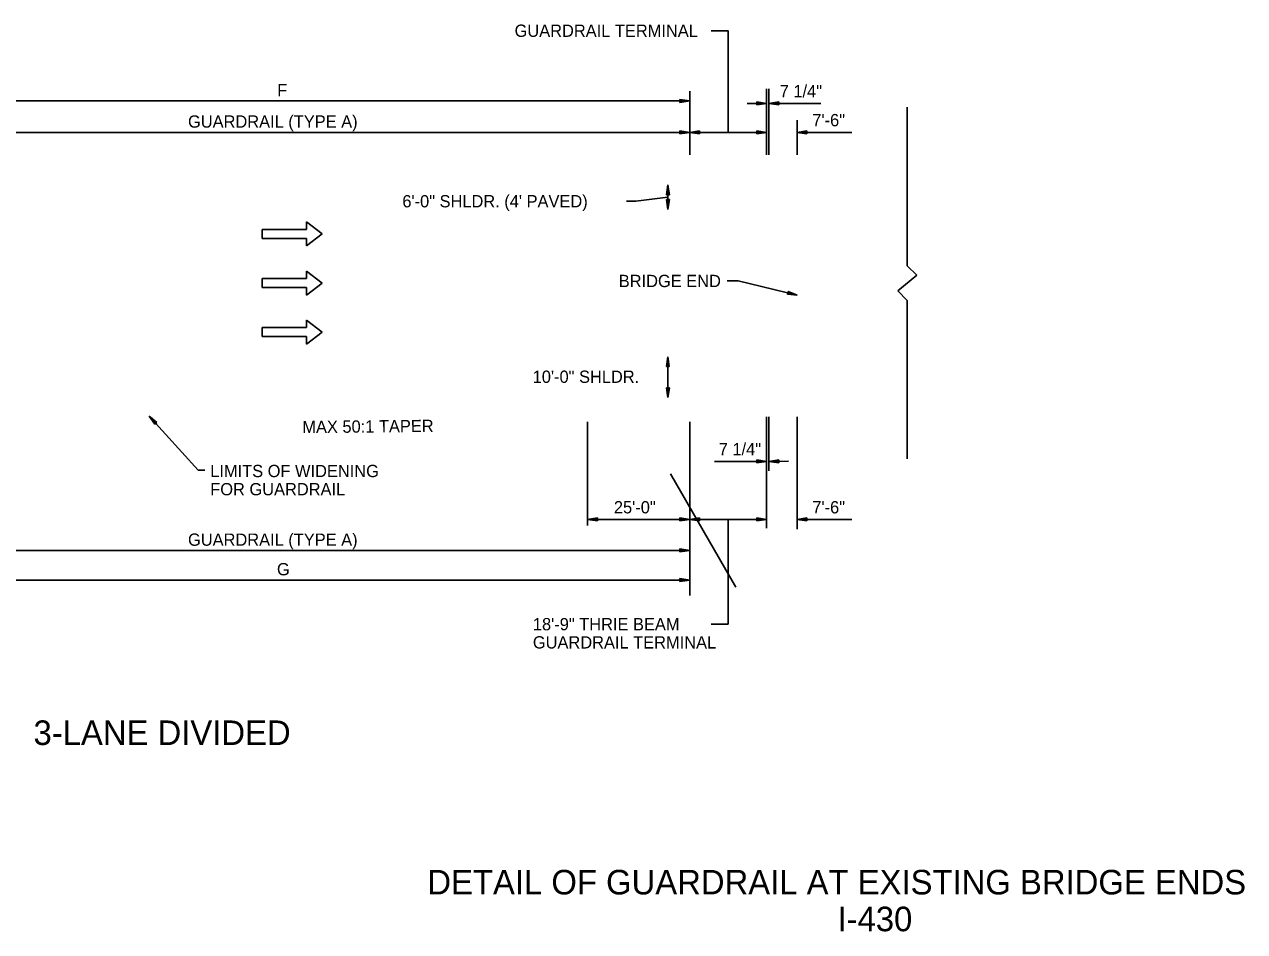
# Model space of a CAD drawing. Extents: x 1373853 to 1374003, y 380191 to 380927.
# Drawn here: x 1373883.7 to 1373943.4, y 380192.7 to 380237.1 of the extents above; entities that cross this region are included whole.
import ezdxf

# ---------------------------------------------------------------- set-up
doc = ezdxf.new("R2010")
doc.units = 0
for name, color, linetype in [('2', 7, 'Continuous'), ('7', 7, 'Continuous'), ('8', 7, 'Continuous'), ('Default', 7, 'Continuous'), ('E_Existing ROW', 7, 'Continuous'), ('R_Guardrail_Widening', 7, 'Continuous')]:
    doc.layers.add(name, color=color, linetype=linetype)

msp = doc.modelspace()

# ---------------------------------------------------------------- linework, layer by layer
at = {"layer": '2'}
for p, q in [((1373916.236, 380230.714), (1373916.236, 380233.821)), ((1373919.986, 380230.714), (1373919.986, 380233.941)), ((1373920.107, 380230.714), (1373920.107, 380233.941)), ((1373876.236, 380233.341), (1373916.236, 380233.341)), ((1373919.986, 380233.22), (1373919.045, 380233.22)), ((1373922.65, 380233.22), (1373920.107, 380233.22)), ((1373921.486, 380230.714), (1373921.486, 380232.406)), ((1373876.236, 380231.806), (1373916.236, 380231.806)), ((1373916.236, 380231.806), (1373919.986, 380231.806)), ((1373921.486, 380231.806), (1373924.16, 380231.806)), ((1373915.169, 380228.041), (1373915.166, 380229.241)), ((1373918.056, 380224.543), (1373918.603, 380224.543)), ((1373921.486, 380223.854), (1373918.603, 380224.543)), ((1373915.169, 380218.841), (1373915.164, 380220.841)), ((1373889.802, 380217.937), (1373892.201, 380215.286)), ((1373911.236, 380212.592), (1373911.236, 380217.66)), ((1373916.236, 380209.174), (1373916.236, 380217.66)), ((1373919.986, 380212.463), (1373919.986, 380217.902)), ((1373920.107, 380215.258), (1373920.107, 380217.902)), ((1373921.486, 380212.402), (1373921.486, 380217.902)), ((1373917.442, 380215.722), (1373919.986, 380215.722)), ((1373920.107, 380215.722), (1373921.067, 380215.725)), ((1373892.201, 380215.286), (1373892.52, 380215.286)), ((1373911.236, 380212.881), (1373916.236, 380212.881)), ((1373916.236, 380212.881), (1373919.986, 380212.881)), ((1373921.486, 380212.881), (1373924.16, 380212.881)), ((1373876.236, 380211.366), (1373916.236, 380211.366)), ((1373876.236, 380209.921), (1373916.236, 380209.921))]:
    msp.add_line(p, q, dxfattribs=at)
for points in [[(1373918.111, 380231.806), (1373918.111, 380236.776), (1373917.276, 380236.776)], [(1373913.145, 380228.441), (1373913.593, 380228.441), (1373915.167, 380228.641)], [(1373918.111, 380212.881), (1373918.111, 380207.765), (1373917.276, 380207.765)]]:
    msp.add_lwpolyline(points, dxfattribs=at)
at = {"layer": '7'}
for p, q in [((1373915.756, 380233.415), (1373916.236, 380233.341)), ((1373915.756, 380233.415), (1373915.756, 380233.269)), ((1373915.756, 380233.4), (1373916.155, 380233.341)), ((1373915.756, 380233.388), (1373916.073, 380233.341)), ((1373915.756, 380233.376), (1373915.992, 380233.341)), ((1373915.756, 380233.365), (1373915.913, 380233.341)), ((1373915.756, 380233.353), (1373915.832, 380233.341)), ((1373915.756, 380233.269), (1373916.236, 380233.341)), ((1373915.756, 380233.319), (1373915.913, 380233.341)), ((1373915.756, 380233.295), (1373916.073, 380233.341)), ((1373915.756, 380233.281), (1373916.155, 380233.341)), ((1373915.756, 380233.305), (1373915.992, 380233.341)), ((1373915.756, 380233.331), (1373915.832, 380233.341)), ((1373919.506, 380233.294), (1373919.986, 380233.22)), ((1373919.506, 380233.294), (1373919.506, 380233.148)), ((1373919.506, 380233.279), (1373919.905, 380233.22)), ((1373919.506, 380233.268), (1373919.823, 380233.22)), ((1373919.506, 380233.256), (1373919.742, 380233.22)), ((1373919.506, 380233.244), (1373919.663, 380233.22)), ((1373919.506, 380233.232), (1373919.582, 380233.22)), ((1373919.506, 380233.148), (1373919.986, 380233.22)), ((1373919.506, 380233.198), (1373919.663, 380233.22)), ((1373919.506, 380233.174), (1373919.823, 380233.22)), ((1373919.506, 380233.16), (1373919.905, 380233.22)), ((1373919.506, 380233.184), (1373919.742, 380233.22)), ((1373919.506, 380233.21), (1373919.582, 380233.22)), ((1373920.587, 380233.294), (1373920.107, 380233.22)), ((1373920.587, 380233.148), (1373920.107, 380233.22)), ((1373920.587, 380233.279), (1373920.188, 380233.22)), ((1373920.587, 380233.16), (1373920.188, 380233.22)), ((1373920.587, 380233.268), (1373920.269, 380233.22)), ((1373920.587, 380233.174), (1373920.269, 380233.22)), ((1373920.587, 380233.256), (1373920.35, 380233.22)), ((1373920.587, 380233.184), (1373920.35, 380233.22)), ((1373920.587, 380233.244), (1373920.429, 380233.22)), ((1373920.587, 380233.198), (1373920.429, 380233.22)), ((1373920.587, 380233.232), (1373920.51, 380233.22)), ((1373920.587, 380233.21), (1373920.51, 380233.22)), ((1373920.587, 380233.294), (1373920.587, 380233.148)), ((1373915.756, 380231.88), (1373916.236, 380231.806)), ((1373915.756, 380231.88), (1373915.756, 380231.734)), ((1373915.756, 380231.865), (1373916.155, 380231.806)), ((1373915.756, 380231.853), (1373916.073, 380231.806)), ((1373915.756, 380231.841), (1373915.992, 380231.806)), ((1373915.756, 380231.829), (1373915.913, 380231.806)), ((1373915.756, 380231.818), (1373915.832, 380231.806)), ((1373915.756, 380231.734), (1373916.236, 380231.806)), ((1373915.756, 380231.784), (1373915.913, 380231.806)), ((1373915.756, 380231.76), (1373916.073, 380231.806)), ((1373915.756, 380231.746), (1373916.155, 380231.806)), ((1373915.756, 380231.77), (1373915.992, 380231.806)), ((1373915.756, 380231.796), (1373915.832, 380231.806)), ((1373916.716, 380231.88), (1373916.236, 380231.806)), ((1373916.716, 380231.734), (1373916.236, 380231.806)), ((1373916.716, 380231.865), (1373916.317, 380231.806)), ((1373916.716, 380231.746), (1373916.317, 380231.806)), ((1373916.716, 380231.853), (1373916.398, 380231.806)), ((1373916.716, 380231.76), (1373916.398, 380231.806)), ((1373916.716, 380231.841), (1373916.479, 380231.806)), ((1373916.716, 380231.77), (1373916.479, 380231.806)), ((1373916.716, 380231.829), (1373916.558, 380231.806)), ((1373916.716, 380231.784), (1373916.558, 380231.806)), ((1373916.716, 380231.818), (1373916.639, 380231.806)), ((1373916.716, 380231.796), (1373916.639, 380231.806)), ((1373916.716, 380231.88), (1373916.716, 380231.734)), ((1373919.506, 380231.88), (1373919.986, 380231.806)), ((1373919.506, 380231.88), (1373919.506, 380231.734)), ((1373919.506, 380231.865), (1373919.905, 380231.806)), ((1373919.506, 380231.853), (1373919.823, 380231.806)), ((1373919.506, 380231.841), (1373919.742, 380231.806)), ((1373919.506, 380231.829), (1373919.663, 380231.806)), ((1373919.506, 380231.818), (1373919.582, 380231.806)), ((1373919.506, 380231.734), (1373919.986, 380231.806)), ((1373919.506, 380231.784), (1373919.663, 380231.806)), ((1373919.506, 380231.76), (1373919.823, 380231.806)), ((1373919.506, 380231.746), (1373919.905, 380231.806)), ((1373919.506, 380231.77), (1373919.742, 380231.806)), ((1373919.506, 380231.796), (1373919.582, 380231.806)), ((1373921.966, 380231.88), (1373921.486, 380231.806)), ((1373921.966, 380231.734), (1373921.486, 380231.806)), ((1373921.966, 380231.865), (1373921.567, 380231.806)), ((1373921.966, 380231.746), (1373921.567, 380231.806)), ((1373921.966, 380231.853), (1373921.648, 380231.806)), ((1373921.966, 380231.76), (1373921.648, 380231.806)), ((1373921.966, 380231.841), (1373921.729, 380231.806)), ((1373921.966, 380231.77), (1373921.729, 380231.806)), ((1373921.966, 380231.829), (1373921.808, 380231.806)), ((1373921.966, 380231.784), (1373921.808, 380231.806)), ((1373921.966, 380231.818), (1373921.889, 380231.806)), ((1373921.966, 380231.796), (1373921.889, 380231.806)), ((1373921.966, 380231.88), (1373921.966, 380231.734)), ((1373915.094, 380228.761), (1373915.166, 380229.241)), ((1373915.106, 380228.761), (1373915.166, 380229.16)), ((1373915.118, 380228.761), (1373915.166, 380229.079)), ((1373915.13, 380228.761), (1373915.166, 380228.998)), ((1373915.142, 380228.761), (1373915.166, 380228.916)), ((1373915.154, 380228.761), (1373915.166, 380228.838)), ((1373915.237, 380228.761), (1373915.166, 380229.241)), ((1373915.226, 380228.761), (1373915.166, 380229.16)), ((1373915.214, 380228.761), (1373915.166, 380229.079)), ((1373915.202, 380228.761), (1373915.166, 380228.998)), ((1373915.19, 380228.761), (1373915.166, 380228.916)), ((1373915.178, 380228.761), (1373915.166, 380228.838)), ((1373915.237, 380228.761), (1373915.094, 380228.761)), ((1373915.095, 380228.521), (1373915.169, 380228.041)), ((1373915.095, 380228.521), (1373915.24, 380228.521)), ((1373915.109, 380228.521), (1373915.169, 380228.122)), ((1373915.121, 380228.521), (1373915.169, 380228.204)), ((1373915.133, 380228.521), (1373915.169, 380228.285)), ((1373915.145, 380228.521), (1373915.169, 380228.364)), ((1373915.157, 380228.521), (1373915.169, 380228.445)), ((1373915.24, 380228.521), (1373915.169, 380228.041)), ((1373915.19, 380228.521), (1373915.169, 380228.364)), ((1373915.214, 380228.521), (1373915.169, 380228.204)), ((1373915.228, 380228.521), (1373915.169, 380228.122)), ((1373915.205, 380228.521), (1373915.169, 380228.285)), ((1373915.178, 380228.521), (1373915.169, 380228.445)), ((1373921.005, 380223.896), (1373921.038, 380224.035)), ((1373921.032, 380224.012), (1373921.328, 380223.892)), ((1373921.035, 380224.023), (1373921.409, 380223.872)), ((1373921.038, 380224.035), (1373921.486, 380223.854)), ((1373921.005, 380223.896), (1373921.486, 380223.854)), ((1373921.007, 380223.907), (1373921.409, 380223.872)), ((1373921.01, 380223.919), (1373921.328, 380223.892)), ((1373921.013, 380223.93), (1373921.249, 380223.911)), ((1373921.016, 380223.942), (1373921.172, 380223.929)), ((1373921.018, 380223.954), (1373921.093, 380223.948)), ((1373921.023, 380223.974), (1373921.093, 380223.948)), ((1373921.027, 380223.988), (1373921.172, 380223.929)), ((1373921.03, 380224), (1373921.249, 380223.911)), ((1373915.092, 380220.361), (1373915.164, 380220.841)), ((1373915.104, 380220.361), (1373915.164, 380220.76)), ((1373915.116, 380220.361), (1373915.164, 380220.679)), ((1373915.128, 380220.361), (1373915.164, 380220.598)), ((1373915.14, 380220.361), (1373915.164, 380220.516)), ((1373915.152, 380220.361), (1373915.164, 380220.438)), ((1373915.235, 380220.361), (1373915.164, 380220.841)), ((1373915.224, 380220.361), (1373915.164, 380220.76)), ((1373915.212, 380220.361), (1373915.164, 380220.679)), ((1373915.2, 380220.361), (1373915.164, 380220.598)), ((1373915.188, 380220.361), (1373915.164, 380220.516)), ((1373915.176, 380220.361), (1373915.164, 380220.438)), ((1373915.235, 380220.361), (1373915.092, 380220.361)), ((1373915.095, 380219.321), (1373915.169, 380218.841)), ((1373915.095, 380219.321), (1373915.24, 380219.321)), ((1373915.109, 380219.321), (1373915.169, 380218.922)), ((1373915.121, 380219.321), (1373915.169, 380219.004)), ((1373915.133, 380219.321), (1373915.169, 380219.085)), ((1373915.145, 380219.321), (1373915.169, 380219.164)), ((1373915.157, 380219.321), (1373915.169, 380219.245)), ((1373915.24, 380219.321), (1373915.169, 380218.841)), ((1373915.19, 380219.321), (1373915.169, 380219.164)), ((1373915.214, 380219.321), (1373915.169, 380219.004)), ((1373915.228, 380219.321), (1373915.169, 380218.922)), ((1373915.205, 380219.321), (1373915.169, 380219.085)), ((1373915.178, 380219.321), (1373915.169, 380219.245)), ((1373890.177, 380217.628), (1373889.802, 380217.937)), ((1373890.07, 380217.534), (1373889.802, 380217.937)), ((1373890.169, 380217.622), (1373889.857, 380217.879)), ((1373890.081, 380217.54), (1373889.857, 380217.879)), ((1373890.092, 380217.55), (1373889.913, 380217.816)), ((1373890.158, 380217.614), (1373889.913, 380217.816)), ((1373890.15, 380217.605), (1373889.965, 380217.758)), ((1373890.098, 380217.559), (1373889.965, 380217.758)), ((1373890.106, 380217.565), (1373890.018, 380217.698)), ((1373890.139, 380217.597), (1373890.018, 380217.698)), ((1373890.177, 380217.628), (1373890.07, 380217.534)), ((1373890.114, 380217.574), (1373890.074, 380217.637)), ((1373890.133, 380217.586), (1373890.074, 380217.637)), ((1373919.506, 380215.796), (1373919.986, 380215.722)), ((1373919.506, 380215.796), (1373919.506, 380215.651)), ((1373919.506, 380215.782), (1373919.905, 380215.722)), ((1373919.506, 380215.77), (1373919.823, 380215.722)), ((1373919.506, 380215.758), (1373919.742, 380215.722)), ((1373919.506, 380215.746), (1373919.663, 380215.722)), ((1373919.506, 380215.734), (1373919.582, 380215.722)), ((1373919.506, 380215.651), (1373919.986, 380215.722)), ((1373919.506, 380215.701), (1373919.663, 380215.722)), ((1373919.506, 380215.677), (1373919.823, 380215.722)), ((1373919.506, 380215.663), (1373919.905, 380215.722)), ((1373919.506, 380215.687), (1373919.742, 380215.722)), ((1373919.506, 380215.713), (1373919.582, 380215.722)), ((1373920.587, 380215.796), (1373920.107, 380215.722)), ((1373920.587, 380215.651), (1373920.107, 380215.722)), ((1373920.587, 380215.782), (1373920.188, 380215.722)), ((1373920.587, 380215.663), (1373920.188, 380215.722)), ((1373920.587, 380215.77), (1373920.269, 380215.722)), ((1373920.587, 380215.677), (1373920.269, 380215.722)), ((1373920.587, 380215.758), (1373920.35, 380215.722)), ((1373920.587, 380215.687), (1373920.35, 380215.722)), ((1373920.587, 380215.746), (1373920.429, 380215.722)), ((1373920.587, 380215.701), (1373920.429, 380215.722)), ((1373920.587, 380215.734), (1373920.51, 380215.722)), ((1373920.587, 380215.713), (1373920.51, 380215.722)), ((1373920.587, 380215.796), (1373920.587, 380215.651)), ((1373911.716, 380212.956), (1373911.236, 380212.881)), ((1373911.716, 380212.81), (1373911.236, 380212.881)), ((1373911.716, 380212.941), (1373911.317, 380212.881)), ((1373911.716, 380212.822), (1373911.317, 380212.881)), ((1373911.716, 380212.929), (1373911.398, 380212.881)), ((1373911.716, 380212.836), (1373911.398, 380212.881)), ((1373911.716, 380212.917), (1373911.479, 380212.881)), ((1373911.716, 380212.846), (1373911.479, 380212.881)), ((1373911.716, 380212.905), (1373911.558, 380212.881)), ((1373911.716, 380212.86), (1373911.558, 380212.881)), ((1373911.716, 380212.893), (1373911.639, 380212.881)), ((1373911.716, 380212.872), (1373911.639, 380212.881)), ((1373911.716, 380212.956), (1373911.716, 380212.81)), ((1373915.756, 380212.956), (1373916.236, 380212.881)), ((1373915.756, 380212.956), (1373915.756, 380212.81)), ((1373915.756, 380212.941), (1373916.155, 380212.881)), ((1373915.756, 380212.929), (1373916.073, 380212.881)), ((1373915.756, 380212.917), (1373915.992, 380212.881)), ((1373915.756, 380212.905), (1373915.913, 380212.881)), ((1373915.756, 380212.893), (1373915.832, 380212.881)), ((1373915.756, 380212.81), (1373916.236, 380212.881)), ((1373915.756, 380212.86), (1373915.913, 380212.881)), ((1373915.756, 380212.836), (1373916.073, 380212.881)), ((1373915.756, 380212.822), (1373916.155, 380212.881)), ((1373915.756, 380212.846), (1373915.992, 380212.881)), ((1373915.756, 380212.872), (1373915.832, 380212.881)), ((1373916.716, 380212.956), (1373916.236, 380212.881)), ((1373916.716, 380212.81), (1373916.236, 380212.881)), ((1373916.716, 380212.941), (1373916.317, 380212.881)), ((1373916.716, 380212.822), (1373916.317, 380212.881)), ((1373916.716, 380212.929), (1373916.398, 380212.881)), ((1373916.716, 380212.836), (1373916.398, 380212.881)), ((1373916.716, 380212.917), (1373916.479, 380212.881)), ((1373916.716, 380212.846), (1373916.479, 380212.881)), ((1373916.716, 380212.905), (1373916.558, 380212.881)), ((1373916.716, 380212.86), (1373916.558, 380212.881)), ((1373916.716, 380212.893), (1373916.639, 380212.881)), ((1373916.716, 380212.872), (1373916.639, 380212.881)), ((1373916.716, 380212.956), (1373916.716, 380212.81)), ((1373919.506, 380212.956), (1373919.986, 380212.881)), ((1373919.506, 380212.956), (1373919.506, 380212.81)), ((1373919.506, 380212.941), (1373919.905, 380212.881)), ((1373919.506, 380212.929), (1373919.823, 380212.881)), ((1373919.506, 380212.917), (1373919.742, 380212.881)), ((1373919.506, 380212.905), (1373919.663, 380212.881)), ((1373919.506, 380212.893), (1373919.582, 380212.881)), ((1373919.506, 380212.81), (1373919.986, 380212.881)), ((1373919.506, 380212.86), (1373919.663, 380212.881)), ((1373919.506, 380212.836), (1373919.823, 380212.881)), ((1373919.506, 380212.822), (1373919.905, 380212.881)), ((1373919.506, 380212.846), (1373919.742, 380212.881)), ((1373919.506, 380212.872), (1373919.582, 380212.881)), ((1373921.966, 380212.956), (1373921.486, 380212.881)), ((1373921.966, 380212.81), (1373921.486, 380212.881)), ((1373921.966, 380212.941), (1373921.567, 380212.881)), ((1373921.966, 380212.822), (1373921.567, 380212.881)), ((1373921.966, 380212.929), (1373921.648, 380212.881)), ((1373921.966, 380212.836), (1373921.648, 380212.881)), ((1373921.966, 380212.917), (1373921.729, 380212.881)), ((1373921.966, 380212.846), (1373921.729, 380212.881)), ((1373921.966, 380212.905), (1373921.808, 380212.881)), ((1373921.966, 380212.86), (1373921.808, 380212.881)), ((1373921.966, 380212.893), (1373921.889, 380212.881)), ((1373921.966, 380212.872), (1373921.889, 380212.881)), ((1373921.966, 380212.956), (1373921.966, 380212.81)), ((1373915.756, 380211.44), (1373916.236, 380211.366)), ((1373915.756, 380211.44), (1373915.756, 380211.294)), ((1373915.756, 380211.425), (1373916.155, 380211.366)), ((1373915.756, 380211.413), (1373916.073, 380211.366)), ((1373915.756, 380211.401), (1373915.992, 380211.366)), ((1373915.756, 380211.39), (1373915.913, 380211.366)), ((1373915.756, 380211.378), (1373915.832, 380211.366)), ((1373915.756, 380211.294), (1373916.236, 380211.366)), ((1373915.756, 380211.344), (1373915.913, 380211.366)), ((1373915.756, 380211.32), (1373916.073, 380211.366)), ((1373915.756, 380211.306), (1373916.155, 380211.366)), ((1373915.756, 380211.33), (1373915.992, 380211.366)), ((1373915.756, 380211.356), (1373915.832, 380211.366)), ((1373915.756, 380209.995), (1373916.236, 380209.921)), ((1373915.756, 380209.995), (1373915.756, 380209.849)), ((1373915.756, 380209.981), (1373916.155, 380209.921)), ((1373915.756, 380209.969), (1373916.073, 380209.921)), ((1373915.756, 380209.957), (1373915.992, 380209.921)), ((1373915.756, 380209.945), (1373915.913, 380209.921)), ((1373915.756, 380209.933), (1373915.832, 380209.921)), ((1373915.756, 380209.849), (1373916.236, 380209.921)), ((1373915.756, 380209.9), (1373915.913, 380209.921)), ((1373915.756, 380209.876), (1373916.073, 380209.921)), ((1373915.756, 380209.861), (1373916.155, 380209.921)), ((1373915.756, 380209.885), (1373915.992, 380209.921)), ((1373915.756, 380209.912), (1373915.832, 380209.921))]:
    msp.add_line(p, q, dxfattribs=at)
at = {"layer": 'Default'}
for p, q in [((1373897.492, 380227.061), (1373895.331, 380227.061)), ((1373895.331, 380227.061), (1373895.331, 380226.621)), ((1373897.492, 380227.429), (1373897.492, 380227.061)), ((1373897.492, 380227.429), (1373898.255, 380226.841)), ((1373897.492, 380226.621), (1373895.331, 380226.621)), ((1373898.255, 380226.841), (1373897.492, 380226.253)), ((1373897.492, 380226.621), (1373897.492, 380226.253)), ((1373897.492, 380224.661), (1373895.331, 380224.661)), ((1373895.331, 380224.661), (1373895.331, 380224.221)), ((1373897.492, 380225.029), (1373897.492, 380224.661)), ((1373897.492, 380225.029), (1373898.255, 380224.441)), ((1373897.492, 380224.221), (1373895.331, 380224.221)), ((1373898.255, 380224.441), (1373897.492, 380223.853)), ((1373897.492, 380224.221), (1373897.492, 380223.853)), ((1373897.492, 380222.261), (1373895.331, 380222.261)), ((1373895.331, 380222.261), (1373895.331, 380221.821)), ((1373897.492, 380222.629), (1373897.492, 380222.261)), ((1373897.492, 380222.629), (1373898.255, 380222.041)), ((1373897.492, 380221.821), (1373895.331, 380221.821)), ((1373898.255, 380222.041), (1373897.492, 380221.453)), ((1373897.492, 380221.821), (1373897.492, 380221.453))]:
    msp.add_line(p, q, dxfattribs=at)
at = {"layer": 'E_Existing ROW'}
msp.add_lwpolyline([(1373915.286, 380215.114), (1373918.482, 380209.579)], dxfattribs=at)
at = {"layer": 'R_Guardrail_Widening'}
for p, q in [((1373926.871, 380225.288), (1373926.871, 380233.041)), ((1373927.337, 380224.822), (1373926.871, 380225.288)), ((1373926.405, 380224.06), (1373927.337, 380224.822)), ((1373926.871, 380223.594), (1373926.405, 380224.06)), ((1373926.871, 380215.841), (1373926.871, 380223.594))]:
    msp.add_line(p, q, dxfattribs=at)

# ---------------------------------------------------------------- texts
at = {"layer": '2'}
for s, rotation, p in [('GUARDRAIL TERMINAL', 359.99997, (1373907.669, 380236.476)), ('F', 0.00003, (1373896.063, 380233.572)), ('7 1/4"', 359.99997, (1373920.632, 380233.52)), ('GUARDRAIL (TYPE A)', 0.00003, (1373891.7, 380232.037)), ('7\'-6"', 0.00003, (1373922.227, 380232.106)), ('MAX 50:1 TAPER', 0.51065, (1373897.291, 380217.103)), ('7 1/4"', 0.00003, (1373917.651, 380216.022)), ('LIMITS OF WIDENING', 0.00003, (1373892.787, 380214.953)), ('FOR GUARDRAIL', 0.00003, (1373892.787, 380214.063)), ('25\'-0"', 0.00003, (1373912.524, 380213.181)), ('7\'-6"', 0.00003, (1373922.227, 380213.181)), ('GUARDRAIL (TYPE A)', 0.00003, (1373891.7, 380211.597)), ('G', 0.00003, (1373896.049, 380210.152)), ('18\'-9" THRIE BEAM', 0.00003, (1373908.563, 380207.465)), ('GUARDRAIL TERMINAL', 0.00003, (1373908.563, 380206.575))]:
    msp.add_text(s, height=0.6, rotation=rotation, dxfattribs=at).set_placement(p)
for s, p in [('6\'-0" SHLDR. (4\' PAVED)', (1373902.18, 380228.141)), ('BRIDGE END', (1373912.763, 380224.243)), ('10\'-0" SHLDR.', (1373908.553, 380219.561))]:
    msp.add_text(s, height=0.6, dxfattribs=at).set_placement(p)
at = {"layer": '8'}
for s, p in [('3-LANE DIVIDED', (1373884.145, 380201.858)), ('DETAIL OF GUARDRAIL AT EXISTING BRIDGE ENDS', (1373903.403, 380194.553)), ('I-430', (1373923.458, 380192.753))]:
    msp.add_text(s, height=1.2, rotation=0.00003, dxfattribs=at).set_placement(p)

doc.saveas('drawing.dxf')
